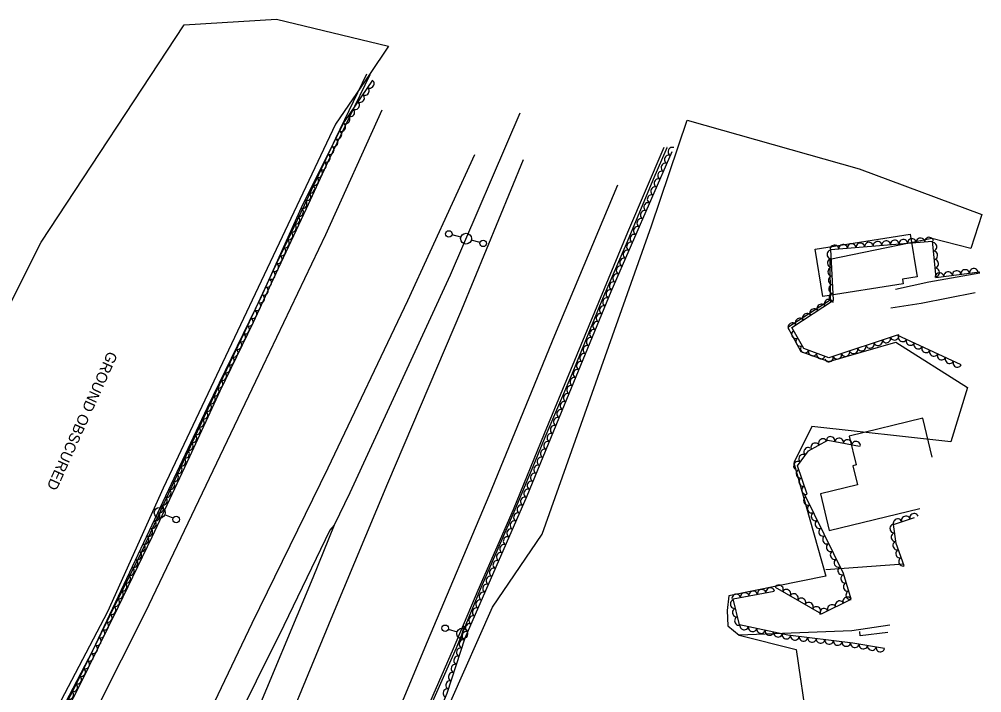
# Model space of a CAD drawing. Extents: x 1722896 to 1754269, y 648279 to 666297.
# Drawn here: x 1726001.6 to 1726447.8, y 665984.4 to 666296.7 of the extents above; entities that cross this region are included whole.
import ezdxf

# ---------------------------------------------------------------- set-up
doc = ezdxf.new("R2010")
doc.units = 0
for name, color, linetype in [('DESIGN - CENTERLINE - Proposed Text', 7, 'Continuous'), ('DESIGN - SCRATCH - User 1', 7, 'Continuous'), ('SURVEY - CENTERLINE - Preliminary', 7, 'Continuous'), ('SURVEY - CENTERLINE - Preliminary Text', 7, 'Continuous'), ('SURVEY - DTM - Breaklines', 7, 'Continuous'), ('SURVEY - VEGETATION - Features with Text', 7, 'Continuous')]:
    doc.layers.add(name, color=color, linetype=linetype)

msp = doc.modelspace()

# ---------------------------------------------------------------- linework, layer by layer
at = {"layer": 'DESIGN - CENTERLINE - Proposed Text'}
msp.add_lwpolyline([(1726411.43, 666174.09), (1726374.08, 666168.12), (1726370.58, 666190.07), (1726414.65, 666197.11), (1726417.82, 666177.27), (1726411.09, 666176.2)], close=True, dxfattribs=at)
msp.add_lwpolyline([(1726424.86, 666093.62), (1726420.42, 666111.7), (1726386.39, 666103.35), (1726389.66, 666090.05), (1726388.06, 666089.66), (1726390.21, 666080.87), (1726372.98, 666076.64), (1726377.15, 666059.63), (1726419.11, 666069.92)], dxfattribs=at)
at = {"layer": 'DESIGN - SCRATCH - User 1'}
for points in [[(1725883.56, 665714.53), (1725900.67, 665746.94), (1725917.36, 665777.04), (1725931.18, 665803.31), (1725946.97, 665833.49), (1725965.25, 665868.17), (1725980.22, 665896.05), (1725996.27, 665927.26), (1726012.08, 665957.42), (1726027.88, 665987.99), (1726043.63, 666020.12), (1726058.6, 666050.26), (1726072.81, 666080.93), (1726089.38, 666116.54), (1726106.29, 666152.02), (1726119.61, 666180.7), (1726133.9, 666210.49), (1726148.45, 666241.52), (1726162.75, 666271.37)], [(1726164.02, 666270.93), (1726164.1, 666270.91), (1726154.69, 666251.41), (1726144.81, 666230.97), (1726134.69, 666208.87), (1726119.39, 666176.13), (1726110.05, 666156.17), (1726094.55, 666124.21), (1726080.52, 666093.87), (1726063.12, 666056.57), (1726047.46, 666024.21), (1726028.85, 665986.55), (1726011.41, 665952.74), (1725995.45, 665922.56), (1725980.72, 665894.19), (1725962.44, 665858.67), (1725944.03, 665824.25), (1725926.59, 665791.37), (1725903.76, 665748.94), (1725885.5, 665714.32)], [(1726233.62, 666253.16), (1726201.31, 666178.11), (1726154.84, 666077.17), (1726147.6, 666062.13)], [(1726300.44, 666237.29), (1726283.51, 666197.79), (1726263.83, 666150.03), (1726245, 666104.41), (1726230.51, 666069.31), (1726214.28, 666031.83), (1726202.77, 666004.85), (1726189.1, 665973.59), (1726172.4, 665934.65), (1726153.3, 665887.93), (1726132.59, 665839.31), (1726115.52, 665798.74), (1726093.57, 665745.47), (1726077.37, 665704.51), (1726077.38, 665704.5)], [(1726078.35, 665704.21), (1726093.86, 665743.33), (1726117.97, 665802.41), (1726147.3, 665871.37), (1726171.04, 665928.18), (1726186.68, 665965.5), (1726204.36, 666005.29), (1726215.74, 666033.18), (1726231.56, 666069.41), (1726240.59, 666091.2), (1726245.47, 666102.95), (1726258.06, 666132.64), (1726272.08, 666167.16), (1726283.62, 666193.58), (1726295.54, 666222.26), (1726301.98, 666237.23), (1726301.85, 666237.25)], [(1726147.6, 666062.13), (1726145.65, 666059.78), (1726124.34, 666015.55), (1726098.62, 665964.01), (1726073.03, 665911.1), (1726048.21, 665862.22), (1726021.75, 665810.59), (1725987.72, 665743.04), (1725975.37, 665718.07)], [(1726147.6, 666062.13), (1726137.78, 666037.68), (1726108.88, 665968.53), (1726080.69, 665900.96), (1726054.42, 665838.24), (1726033.77, 665788.5), (1726011.64, 665736.82), (1726002.55, 665714.94)]]:
    msp.add_lwpolyline(points, dxfattribs=at)
at = {"layer": 'SURVEY - CENTERLINE - Preliminary'}
for points in [[(1725883.45, 665714.66), (1725873.26, 665694.89), (1725857.67, 665676.84), (1725800.05, 665688.95), (1725753.69, 665709.28), (1725827.03, 665844.09), (1725870.83, 665843.31), (1725892.58, 665904.51), (1725867.01, 665915.72), (1725946.92, 666064.16), (1726011.72, 666193.28), (1726078.11, 666294.1), (1726120.84, 666296.69), (1726172.83, 666284.28)], [(1726172.83, 666284.28), (1726163.93, 666271.12)], [(1726163.93, 666271.12), (1726148.28, 666248.01), (1726068.35, 666079.3), (1726042.5, 666021.89), (1725999.33, 665939.48), (1725962.2, 665865.36), (1725944.36, 665875.69), (1725920.63, 665859.54), (1725897, 665804.15), (1725915.53, 665776.91), (1725883.47, 665714.69)], [(1726201.66, 665980.58), (1726221.01, 666024.13), (1726243.97, 666057.93), (1726294.64, 666200.84), (1726311.32, 666249.85)], [(1726311.32, 666249.85), (1726390.98, 666227.32), (1726447.81, 666206.24), (1726442.75, 666190.38), (1726424.71, 666195.09), (1726377.42, 666185.26), (1726377.51, 666166.41), (1726357.86, 666153.81), (1726363.88, 666142.7), (1726376.86, 666137.97), (1726408.04, 666146.96), (1726441.28, 666126), (1726433.41, 666100.73), (1726369.06, 666107.92), (1726360.63, 666090.99), (1726375.58, 666038.55), (1726330.58, 666029.42), (1726329.77, 666022.62), (1726330.05, 666015.5), (1726335.31, 666011.17), (1726361.83, 666004.42), (1726366.89, 665969.61)]]:
    msp.add_lwpolyline(points, dxfattribs=at)
at = {"layer": 'SURVEY - CENTERLINE - Preliminary Text'}
for points in [[(1726169.69, 666254.61), (1726143.63, 666196.79), (1726111.12, 666128.78), (1726059.94, 666021.58), (1726004.19, 665910.82), (1725956.15, 665817.3), (1725918.15, 665747.27)], [(1726212.66, 666233.87), (1726181.61, 666166.13), (1726144.69, 666088.52), (1726109.49, 666016.58), (1726085.79, 665966.87), (1726053.61, 665902.62), (1726012.25, 665819.21), (1725975.45, 665747.31)], [(1726235.28, 666231.45), (1726206.7, 666162.01), (1726172.39, 666081.46), (1726146.79, 666020.44), (1726115.21, 665943.7), (1726071.8, 665842.22), (1726045.03, 665778.6), (1726017.64, 665714.05), (1726016.73, 665711.93)], [(1726278.9, 666219.71), (1726249.81, 666150.14), (1726219.34, 666075.73), (1726190.68, 666008.04), (1726168.67, 665955), (1726137.7, 665880.57), (1726115.77, 665829.08), (1726093, 665773.8), (1726068.63, 665714.27), (1726064.97, 665705.21)], [(1726446.94, 666179.01), (1726423.24, 666174.77), (1726407.76, 666171.45)], [(1726444.83, 666169.8), (1726419.74, 666164.86), (1726405.68, 666162.82)], [(1726411.52, 666044.04), (1726375.46, 666041.47)], [(1726405.13, 666015.72), (1726387.59, 666013.1), (1726335.31, 666011.17)], [(1726404.23, 666012.32), (1726391.48, 666010.83), (1726391.25, 666012.87)]]:
    msp.add_lwpolyline(points, dxfattribs=at)
at = {"layer": 'SURVEY - DTM - Breaklines'}
for p, q in [((1726206.33, 666195.63), (1726202.23, 666196.75)), ((1726215.25, 666193.18), (1726211.15, 666194.31)), ((1726066.73, 666067.9), (1726068.15, 666071.37)), ((1726066.73, 666067.9), (1726065.3, 666064.43)), ((1726072.97, 666065.34), (1726069.04, 666066.95)), ((1726200.52, 666013.89), (1726204.57, 666012.61)), ((1726206.96, 666011.85), (1726208.09, 666015.43)), ((1726206.96, 666011.85), (1726205.82, 666008.28))]:
    msp.add_line(p, q, dxfattribs=at)
for centre, radius in [((1726200.78, 666197.15), 1.5), ((1726208.74, 666194.97), 2.5), ((1726216.7, 666192.79), 1.5), ((1726066.73, 666067.9), 2.5), ((1726074.36, 666064.77), 1.5), ((1726199.09, 666014.35), 1.5), ((1726206.96, 666011.85), 2.5)]:
    msp.add_circle(centre, radius, dxfattribs=at)
at = {"layer": 'SURVEY - VEGETATION - Features with Text'}
for points in [[(1726165.31, 666268.38), (1726152.25, 666249.2), (1726132.96, 666210.67), (1726113.81, 666167.99), (1726088.69, 666116.56), (1726059.21, 666054.01), (1726035.59, 666003.82), (1726015.62, 665965.66), (1725995.03, 665925.63), (1725970.03, 665874.92), (1725948.85, 665838.58), (1725927.55, 665794.1), (1725915.96, 665771.73), (1725888.7, 665724.31), (1725873.18, 665693.81), (1725858.78, 665676.03), (1725822.9, 665675.22), (1725797.45, 665684.88), (1725764.14, 665700), (1725758.83, 665703.58)], [(1726074.19, 665687.95), (1726082.24, 665702.73), (1726096.88, 665735.22), (1726119.23, 665788.21), (1726139.09, 665838.35), (1726163.21, 665897.7), (1726181.83, 665941.13), (1726200.02, 665984.31), (1726208.39, 666009.97), (1726237, 666075.72), (1726254.45, 666117.9), (1726275.96, 666170.44), (1726304.28, 666235.39)], [(1726438.27, 666136.48), (1726408.56, 666150.27), (1726376.98, 666139.77), (1726365.26, 666144.09), (1726359.75, 666153.82), (1726379.03, 666166.38), (1726377.88, 666189.94), (1726424.8, 666193.83), (1726426.53, 666177.03), (1726446.91, 666179.57)], [(1726366.87, 666076.47), (1726362.47, 666089.66), (1726367.56, 666096.59), (1726376.43, 666101.55), (1726391.13, 666098.83)], [(1726352.11, 666033.42), (1726373.56, 666021.06), (1726387.31, 666027.83), (1726383.65, 666039.79), (1726365.72, 666076.19)], [(1726411.88, 666043.28), (1726408.17, 666053.7), (1726406.85, 666062.5), (1726416.68, 666065.74)], [(1726402.78, 666004.99), (1726388.09, 666007.46), (1726357.86, 666011.15), (1726335.54, 666015.98), (1726332.56, 666027.95), (1726351.61, 666031.51)]]:
    msp.add_lwpolyline(points, dxfattribs=at)
for centre, major_axis in [((1726164.19, 666266.72), (-1.13, -1.65)), ((1726161.93, 666263.42), (-1.13, -1.65)), ((1726159.68, 666260.11), (-1.13, -1.65)), ((1726155.18, 666253.5), (-1.13, -1.65)), ((1726157.43, 666256.81), (-1.13, -1.65)), ((1726152.93, 666250.19), (-1.13, -1.65)), ((1726151, 666246.7), (-0.9, -1.79)), ((1726147.42, 666239.54), (-0.9, -1.79)), ((1726149.21, 666243.12), (-0.9, -1.79)), ((1726145.62, 666235.97), (-0.9, -1.79)), ((1726304.26, 666235.34), (0.8, 1.83)), ((1726143.83, 666232.39), (-0.9, -1.79)), ((1726302.66, 666231.68), (0.8, 1.83)), ((1726142.04, 666228.81), (-0.9, -1.79)), ((1726301.07, 666228.01), (0.8, 1.83)), ((1726138.46, 666221.66), (-0.9, -1.79)), ((1726140.25, 666225.24), (-0.9, -1.79)), ((1726297.87, 666220.68), (0.8, 1.83)), ((1726299.47, 666224.35), (0.8, 1.83)), ((1726136.67, 666218.08), (-0.9, -1.79)), ((1726296.27, 666217.01), (0.8, 1.83)), ((1726134.88, 666214.51), (-0.9, -1.79)), ((1726294.67, 666213.35), (0.8, 1.83)), ((1726133.09, 666210.93), (-0.9, -1.79)), ((1726293.07, 666209.68), (0.8, 1.83)), ((1726129.8, 666203.64), (-0.82, -1.82)), ((1726131.44, 666207.29), (-0.82, -1.82)), ((1726291.47, 666206.01), (0.8, 1.83)), ((1726128.17, 666199.99), (-0.82, -1.82)), ((1726288.28, 666198.68), (0.8, 1.83)), ((1726289.87, 666202.35), (0.8, 1.83)), ((1726126.53, 666196.34), (-0.82, -1.82)), ((1726286.68, 666195.01), (0.8, 1.83)), ((1726124.89, 666192.69), (-0.82, -1.82)), ((1726285.08, 666191.35), (0.8, 1.83)), ((1726379.57, 666190.08), (1.99, 0.17)), ((1726383.56, 666190.41), (1.99, 0.17)), ((1726387.54, 666190.74), (1.99, 0.17)), ((1726391.53, 666191.07), (1.99, 0.17)), ((1726395.52, 666191.4), (1.99, 0.17)), ((1726399.5, 666191.73), (1.99, 0.17)), ((1726403.49, 666192.06), (1.99, 0.17)), ((1726407.47, 666192.39), (1.99, 0.17)), ((1726411.46, 666192.73), (1.99, 0.17)), ((1726415.45, 666193.06), (1.99, 0.17)), ((1726419.43, 666193.39), (1.99, 0.17)), ((1726423.42, 666193.72), (1.99, 0.17)), ((1726425.07, 666191.23), (0.2, -1.99)), ((1726123.25, 666189.04), (-0.82, -1.82)), ((1726283.48, 666187.68), (0.8, 1.83)), ((1726377.99, 666187.64), (-0.1, 2)), ((1726425.48, 666187.26), (0.2, -1.99)), ((1726119.98, 666181.74), (-0.82, -1.82)), ((1726121.62, 666185.39), (-0.82, -1.82)), ((1726281.88, 666184.01), (0.8, 1.83)), ((1726378.19, 666183.64), (-0.1, 2)), ((1726425.89, 666183.28), (0.2, -1.99)), ((1726118.34, 666178.09), (-0.82, -1.82)), ((1726278.68, 666176.68), (0.8, 1.83)), ((1726280.28, 666180.35), (0.8, 1.83)), ((1726378.38, 666179.65), (-0.1, 2)), ((1726426.3, 666179.3), (0.2, -1.99)), ((1726428.24, 666177.24), (1.98, 0.25)), ((1726432.21, 666177.73), (1.98, 0.25)), ((1726436.17, 666178.23), (1.98, 0.25)), ((1726440.14, 666178.72), (1.98, 0.25)), ((1726444.11, 666179.22), (1.98, 0.25)), ((1726116.7, 666174.44), (-0.82, -1.82)), ((1726277.08, 666173.01), (0.8, 1.83)), ((1726378.58, 666175.65), (-0.1, 2)), ((1726115.07, 666170.79), (-0.82, -1.82)), ((1726275.51, 666169.34), (0.76, 1.85)), ((1726378.77, 666171.65), (-0.1, 2)), ((1726378.97, 666167.66), (-0.1, 2)), ((1726111.65, 666163.56), (-0.88, -1.8)), ((1726113.4, 666167.16), (-0.88, -1.8)), ((1726273.99, 666165.63), (0.76, 1.85)), ((1726376.75, 666164.9), (1.68, 1.09)), ((1726109.89, 666159.97), (-0.88, -1.8)), ((1726270.96, 666158.23), (0.76, 1.85)), ((1726272.48, 666161.93), (0.76, 1.85)), ((1726366.7, 666158.35), (1.68, 1.09)), ((1726370.05, 666160.53), (1.68, 1.09)), ((1726373.4, 666162.71), (1.68, 1.09)), ((1726108.14, 666156.37), (-0.88, -1.8)), ((1726269.45, 666154.53), (0.76, 1.85)), ((1726359.99, 666153.98), (1.68, 1.09)), ((1726363.35, 666156.16), (1.68, 1.09)), ((1726106.38, 666152.78), (-0.88, -1.8)), ((1726267.93, 666150.83), (0.76, 1.85)), ((1726361.57, 666150.6), (-0.99, 1.74)), ((1726102.87, 666145.59), (-0.88, -1.8)), ((1726104.63, 666149.18), (-0.88, -1.8)), ((1726266.42, 666147.12), (0.76, 1.85)), ((1726363.54, 666147.12), (-0.99, 1.74)), ((1726399.79, 666147.35), (-1.9, -0.63)), ((1726403.58, 666148.61), (-1.9, -0.63)), ((1726407.38, 666149.87), (-1.9, -0.63)), ((1726411.06, 666149.11), (-1.81, 0.84)), ((1726414.69, 666147.43), (-1.81, 0.84)), ((1726101.12, 666141.99), (-0.88, -1.8)), ((1726264.9, 666143.42), (0.76, 1.85)), ((1726365.75, 666143.91), (-1.88, 0.69)), ((1726369.5, 666142.53), (-1.88, 0.69)), ((1726384.6, 666142.3), (-1.9, -0.63)), ((1726388.4, 666143.57), (-1.9, -0.63)), ((1726392.19, 666144.83), (-1.9, -0.63)), ((1726395.99, 666146.09), (-1.9, -0.63)), ((1726418.31, 666145.74), (-1.81, 0.84)), ((1726421.94, 666144.06), (-1.81, 0.84)), ((1726425.57, 666142.37), (-1.81, 0.84)), ((1726099.36, 666138.4), (-0.88, -1.8)), ((1726261.87, 666136.02), (0.76, 1.85)), ((1726263.39, 666139.72), (0.76, 1.85)), ((1726373.26, 666141.15), (-1.88, 0.69)), ((1726377.01, 666139.78), (-1.9, -0.63)), ((1726380.81, 666141.04), (-1.9, -0.63)), ((1726429.2, 666140.69), (-1.81, 0.84)), ((1726432.83, 666139.01), (-1.81, 0.84)), ((1726436.46, 666137.32), (-1.81, 0.84)), ((1726097.6, 666134.81), (-0.88, -1.8)), ((1726260.36, 666132.32), (0.76, 1.85)), ((1726094.09, 666127.62), (-0.88, -1.8)), ((1726095.85, 666131.21), (-0.88, -1.8)), ((1726258.84, 666128.62), (0.76, 1.85)), ((1726092.34, 666124.02), (-0.88, -1.8)), ((1726257.33, 666124.91), (0.76, 1.85)), ((1726090.58, 666120.43), (-0.88, -1.8)), ((1726255.81, 666121.21), (0.76, 1.85)), ((1726088.83, 666116.83), (-0.88, -1.8)), ((1726252.76, 666113.81), (0.76, 1.85)), ((1726254.29, 666117.51), (0.76, 1.85)), ((1726085.41, 666109.6), (-0.85, -1.81)), ((1726087.12, 666113.22), (-0.85, -1.81)), ((1726251.23, 666110.12), (0.76, 1.85)), ((1726083.71, 666105.98), (-0.85, -1.81)), ((1726249.7, 666106.42), (0.76, 1.85)), ((1726082, 666102.36), (-0.85, -1.81)), ((1726248.17, 666102.73), (0.76, 1.85)), ((1726377.74, 666101.31), (1.97, -0.36)), ((1726381.67, 666100.58), (1.97, -0.36)), ((1726080.3, 666098.74), (-0.85, -1.81)), ((1726246.64, 666099.03), (0.76, 1.85)), ((1726367.26, 666096.18), (1.18, 1.61)), ((1726370.61, 666098.3), (1.75, 0.98)), ((1726374.1, 666100.25), (1.75, 0.98)), ((1726385.6, 666099.85), (1.97, -0.36)), ((1726389.54, 666099.12), (1.97, -0.36)), ((1726078.59, 666095.13), (-0.85, -1.81)), ((1726243.58, 666091.64), (0.76, 1.85)), ((1726245.11, 666095.34), (0.76, 1.85)), ((1726364.89, 666092.96), (1.18, 1.61)), ((1726075.18, 666087.89), (-0.85, -1.81)), ((1726076.89, 666091.51), (-0.85, -1.81)), ((1726242.05, 666087.94), (0.76, 1.85)), ((1726362.52, 666089.73), (1.18, 1.61)), ((1726073.48, 666084.27), (-0.85, -1.81)), ((1726240.52, 666084.25), (0.76, 1.85)), ((1726363.7, 666085.95), (-0.63, 1.9)), ((1726071.77, 666080.65), (-0.85, -1.81)), ((1726238.99, 666080.55), (0.76, 1.85)), ((1726364.97, 666082.16), (-0.63, 1.9)), ((1726366.24, 666078.37), (-0.63, 1.9)), ((1726070.07, 666077.04), (-0.85, -1.81)), ((1726237.46, 666076.86), (0.76, 1.85)), ((1726066.65, 666069.8), (-0.85, -1.81)), ((1726068.36, 666073.42), (-0.85, -1.81)), ((1726234.29, 666069.51), (0.8, 1.83)), ((1726235.89, 666073.18), (0.8, 1.83)), ((1726367.12, 666073.35), (-0.88, 1.79)), ((1726368.89, 666069.76), (-0.88, 1.79)), ((1726064.95, 666066.18), (-0.85, -1.81)), ((1726232.7, 666065.84), (0.8, 1.83)), ((1726370.65, 666066.17), (-0.88, 1.79)), ((1726416.39, 666065.64), (1.9, 0.63)), ((1726063.24, 666062.56), (-0.85, -1.81)), ((1726231.1, 666062.18), (0.8, 1.83)), ((1726372.42, 666062.58), (-0.88, 1.79)), ((1726407.14, 666060.56), (-0.29, 1.98)), ((1726408.79, 666063.14), (1.9, 0.63)), ((1726412.59, 666064.39), (1.9, 0.63)), ((1726061.54, 666058.94), (-0.85, -1.81)), ((1726229.51, 666058.51), (0.8, 1.83)), ((1726374.19, 666058.99), (-0.88, 1.79)), ((1726407.73, 666056.6), (-0.29, 1.98)), ((1726058.13, 666051.71), (-0.85, -1.81)), ((1726059.83, 666055.33), (-0.85, -1.81)), ((1726226.31, 666051.17), (0.8, 1.83)), ((1726227.91, 666054.84), (0.8, 1.83)), ((1726375.96, 666055.41), (-0.88, 1.79)), ((1726377.72, 666051.82), (-0.88, 1.79)), ((1726408.52, 666052.7), (-0.67, 1.88)), ((1726056.43, 666048.09), (-0.85, -1.81)), ((1726224.72, 666047.5), (0.8, 1.83)), ((1726379.49, 666048.23), (-0.88, 1.79)), ((1726409.87, 666048.93), (-0.67, 1.88)), ((1726054.72, 666044.47), (-0.85, -1.81)), ((1726223.12, 666043.84), (0.8, 1.83)), ((1726381.26, 666044.64), (-0.88, 1.79)), ((1726411.21, 666045.16), (-0.67, 1.88)), ((1726053.02, 666040.85), (-0.85, -1.81)), ((1726221.53, 666040.17), (0.8, 1.83)), ((1726383.02, 666041.05), (-0.88, 1.79)), ((1726051.31, 666037.23), (-0.85, -1.81)), ((1726219.93, 666036.5), (0.8, 1.83)), ((1726384.41, 666037.31), (-0.59, 1.91)), ((1726047.91, 666029.99), (-0.85, -1.81)), ((1726049.61, 666033.61), (-0.85, -1.81)), ((1726216.74, 666029.16), (0.8, 1.83)), ((1726218.34, 666032.83), (0.8, 1.83)), ((1726341.88, 666029.69), (1.97, 0.37)), ((1726345.81, 666030.43), (1.97, 0.37)), ((1726349.75, 666031.16), (1.97, 0.37)), ((1726353.84, 666032.42), (1.73, -1)), ((1726357.31, 666030.43), (1.73, -1)), ((1726385.58, 666033.49), (-0.59, 1.91)), ((1726386.75, 666029.66), (-0.59, 1.91)), ((1726046.2, 666026.37), (-0.85, -1.81)), ((1726215.14, 666025.5), (0.8, 1.83)), ((1726333.17, 666025.5), (-0.48, 1.94)), ((1726334.02, 666028.22), (1.97, 0.37)), ((1726337.95, 666028.95), (1.97, 0.37)), ((1726360.78, 666028.43), (1.73, -1)), ((1726364.24, 666026.43), (1.73, -1)), ((1726367.71, 666024.44), (1.73, -1)), ((1726381.86, 666025.14), (1.79, 0.88)), ((1726385.45, 666026.91), (1.79, 0.88)), ((1726044.5, 666022.75), (-0.85, -1.81)), ((1726213.55, 666021.83), (0.8, 1.83)), ((1726334.14, 666021.62), (-0.48, 1.94)), ((1726371.17, 666022.44), (1.73, -1)), ((1726374.68, 666021.61), (1.79, 0.88)), ((1726378.27, 666023.38), (1.79, 0.88)), ((1726042.8, 666019.14), (-0.85, -1.81)), ((1726211.95, 666018.16), (0.8, 1.83)), ((1726335.1, 666017.74), (-0.48, 1.94)), ((1726039.39, 666011.9), (-0.85, -1.81)), ((1726041.09, 666015.52), (-0.85, -1.81)), ((1726210.36, 666014.49), (0.8, 1.83)), ((1726337.68, 666015.52), (-1.95, 0.42)), ((1726341.59, 666014.67), (-1.95, 0.42)), ((1726345.5, 666013.83), (-1.95, 0.42)), ((1726349.41, 666012.98), (-1.95, 0.42)), ((1726037.69, 666008.28), (-0.85, -1.81)), ((1726207.44, 666007.05), (0.62, 1.9)), ((1726208.76, 666010.83), (0.8, 1.83)), ((1726353.32, 666012.13), (-1.95, 0.42)), ((1726357.23, 666011.29), (-1.95, 0.42)), ((1726361.19, 666010.74), (-1.99, 0.24)), ((1726365.16, 666010.26), (-1.99, 0.24)), ((1726369.13, 666009.77), (-1.99, 0.24)), ((1726373.1, 666009.29), (-1.99, 0.24)), ((1726377.07, 666008.8), (-1.99, 0.24)), ((1726035.98, 666004.66), (-0.85, -1.81)), ((1726206.2, 666003.25), (0.62, 1.9)), ((1726381.04, 666008.32), (-1.99, 0.24)), ((1726385.01, 666007.84), (-1.99, 0.24)), ((1726388.98, 666007.31), (-1.97, 0.33)), ((1726392.92, 666006.65), (-1.97, 0.33)), ((1726396.87, 666005.98), (-1.97, 0.33)), ((1726400.81, 666005.32), (-1.97, 0.33)), ((1726034.16, 666001.1), (-0.93, -1.77)), ((1726204.96, 665999.45), (0.62, 1.9)), ((1726030.45, 665994.01), (-0.93, -1.77)), ((1726032.31, 665997.55), (-0.93, -1.77)), ((1726203.72, 665995.65), (0.62, 1.9)), ((1726028.6, 665990.47), (-0.93, -1.77)), ((1726202.48, 665991.84), (0.62, 1.9)), ((1726026.74, 665986.92), (-0.93, -1.77)), ((1726199.99, 665984.24), (0.78, 1.84)), ((1726201.24, 665988.04), (0.62, 1.9)), ((1726024.89, 665983.38), (-0.93, -1.77))]:
    msp.add_ellipse(centre, major_axis=major_axis, ratio=0.940188, start_param=0, end_param=3.141593, dxfattribs=at)

# ---------------------------------------------------------------- texts
at = {"layer": 'SURVEY - CENTERLINE - Preliminary'}
msp.add_text('GROUND OBSCURED', height=5, rotation=245.7092, dxfattribs=at).set_placement((1726042.79, 666143.12))

doc.saveas('drawing.dxf')
